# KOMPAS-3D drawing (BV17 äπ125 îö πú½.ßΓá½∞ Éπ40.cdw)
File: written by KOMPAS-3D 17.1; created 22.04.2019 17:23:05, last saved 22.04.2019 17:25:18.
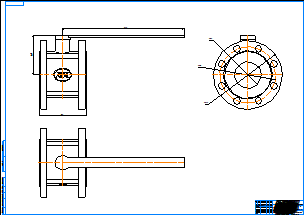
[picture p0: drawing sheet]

Sheet 1: A0, landscape

Title block, sheet 1: name: BV17 Ду125 МФ угл.сталь Ру40; material: Внимание! Данный продукт является объектом авторского права ООО «Торговый Дом АДЛ». / Запрещается изменение, копирование, распространение / (в том числе путем копирования на другие сайты и ресурсы в Интернете) / или любое иное использование информации и объектов без предварительного / согласия правообладателя (ООО «Торговый Дом АДЛ»).; mass: 38,07; sheets: 1; organisation: ООО "Торговый дом АДЛ"; sheet format: A0; stored path: \\adlc.lan\data\АДЛ_ПКД\3D-модели\ADL production\Краны шаровые серии BV\BV17 МФ угл.сталь Ру40\KOMPAS 2D\BV17 Ду125 МФ угл.сталь Ру40.cdw

Views: Вид 1, Проекционный вид 2, Проекционный вид 3
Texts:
  user
Dimensions and other numbers on the sheet: 475; 154,9; 183; 220; 105; 270; 1:1; 1; 38,07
